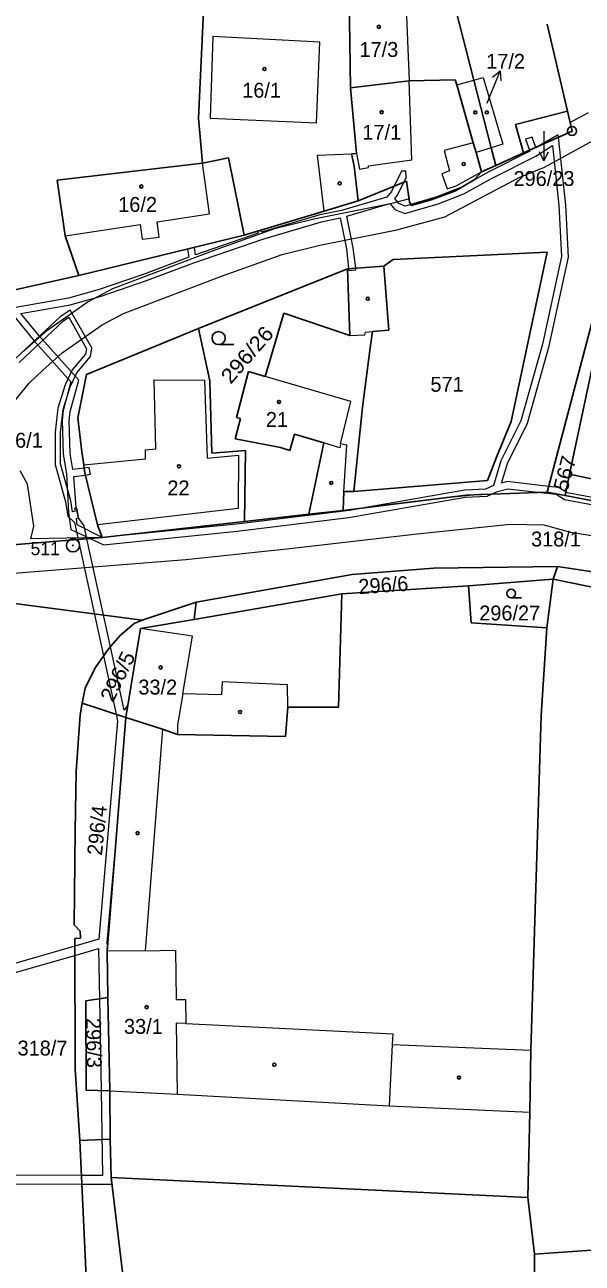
# Model space of a CAD drawing. Extents: x -769392 to -767038, y -1018329 to -1015269.
# Drawn here: x -768447.4 to -768383.8, y -1016351.8 to -1016210.5 of the extents above; entities that cross this region are included whole.
import ezdxf
from ezdxf.enums import TextEntityAlignment as Align

# ---------------------------------------------------------------- set-up
doc = ezdxf.new("R2010")
doc.units = 0
doc.header["$LTSCALE"] = 0.68
for name, color, linetype, lineweight in [('1', 7, 'Continuous', 25), ('13', 7, 'Continuous', 13), ('3', 7, 'Continuous', 25), ('4', 7, 'Continuous', 13), ('5', 7, 'Continuous', 25), ('7', 7, 'Continuous', 13), ('8', 7, 'Continuous', 25)]:
    doc.layers.add(name, color=color, linetype=linetype, lineweight=lineweight)
doc.layers.add('2', color=7, linetype='Continuous')

msp = doc.modelspace()

# ---------------------------------------------------------------- linework, layer by layer
at = {"layer": '1'}
for p, q in [((-768427.58, -1016221.15), (-768426.85, -1016205.24)), ((-768410.25, -1016217.66), (-768410.41, -1016207.35)), ((-768396.18, -1016216.78), (-768398.81, -1016206.49)), ((-768387.82, -1016210.42), (-768385.5, -1016220.32)), ((-768410.25, -1016217.66), (-768403.57, -1016216.87)), ((-768403.57, -1016216.87), (-768398.3, -1016216.77)), ((-768398.3, -1016216.77), (-768398.11, -1016217.33)), ((-768398.11, -1016217.33), (-768396.23, -1016223.95)), ((-768394.2, -1016224.52), (-768396.18, -1016216.78)), ((-768409.58, -1016225.18), (-768410.25, -1016217.66)), ((-768391.42, -1016221.87), (-768385.5, -1016220.32)), ((-768385.5, -1016220.32), (-768384.97, -1016222.6)), ((-768427.14, -1016226.27), (-768427.58, -1016221.15)), ((-768390.51, -1016225.1), (-768391.42, -1016221.87)), ((-768384.97, -1016222.6), (-768390.51, -1016225.1)), ((-768396.23, -1016223.95), (-768395.92, -1016225.04)), ((-768393.68, -1016226.53), (-768394.2, -1016224.52)), ((-768377.38, -1016224.21), (-768387.81, -1016263.79)), ((-768424.16, -1016225.64), (-768427.14, -1016226.27)), ((-768422.37, -1016234.48), (-768424.16, -1016225.64)), ((-768410.13, -1016225.19), (-768409.58, -1016225.18)), ((-768409.84, -1016226.61), (-768410.13, -1016225.19)), ((-768395.92, -1016225.04), (-768395.3, -1016227.26)), ((-768390.51, -1016225.1), (-768393.68, -1016226.53)), ((-768443.71, -1016228.21), (-768427.14, -1016226.27)), ((-768409.37, -1016230.58), (-768409.84, -1016226.61)), ((-768395.3, -1016227.26), (-768396.12, -1016228.18)), ((-768393.68, -1016226.53), (-768395.3, -1016227.26)), ((-768442.8, -1016234.55), (-768443.71, -1016228.21)), ((-768403.85, -1016228.31), (-768409.37, -1016230.58)), ((-768403.53, -1016230.66), (-768403.85, -1016228.31)), ((-768396.12, -1016228.18), (-768398.26, -1016229.41)), ((-768398.26, -1016229.41), (-768401.04, -1016230.45)), ((-768413.24, -1016231.74), (-768409.37, -1016230.58)), ((-768403.33, -1016231.11), (-768403.53, -1016230.66)), ((-768401.04, -1016230.45), (-768403.33, -1016231.11)), ((-768422.37, -1016234.48), (-768413.24, -1016231.74)), ((-768441.25, -1016239.08), (-768442.8, -1016234.55)), ((-768441.25, -1016239.08), (-768422.37, -1016234.48)), ((-768406.45, -1016238.03), (-768405.37, -1016237.26)), ((-768405.37, -1016237.26), (-768387.79, -1016236.4)), ((-768387.79, -1016236.4), (-768391.91, -1016255.72)), ((-768427.58, -1016245.12), (-768410.58, -1016238.33)), ((-768410.58, -1016238.33), (-768406.45, -1016238.03)), ((-768410.58, -1016238.33), (-768410.31, -1016245.94)), ((-768405.88, -1016245.31), (-768406.45, -1016238.03)), ((-768449.37, -1016240.92), (-768441.25, -1016239.08)), ((-768385.26, -1016261.73), (-768380.52, -1016239.41)), ((-768417.87, -1016243.39), (-768419.98, -1016250.59)), ((-768410.31, -1016245.94), (-768417.87, -1016243.39)), ((-768440.38, -1016250.37), (-768427.58, -1016245.12)), ((-768426.31, -1016251.11), (-768427.58, -1016245.12)), ((-768407.99, -1016247.34), (-768407.74, -1016245.47)), ((-768407.74, -1016245.47), (-768405.88, -1016245.31)), ((-768408.88, -1016254.11), (-768407.99, -1016247.34)), ((-768441.37, -1016255.32), (-768440.38, -1016250.37)), ((-768426.05, -1016259.35), (-768426.31, -1016251.11)), ((-768421.9, -1016250.03), (-768423.26, -1016255.27)), ((-768419.98, -1016250.59), (-768421.9, -1016250.03)), ((-768409.86, -1016263.72), (-768408.88, -1016254.11)), ((-768440.91, -1016259.2), (-768441.37, -1016255.32)), ((-768422.79, -1016255.4), (-768423.41, -1016257.71)), ((-768423.26, -1016255.27), (-768422.79, -1016255.4)), ((-768391.91, -1016255.72), (-768393.57, -1016259.81)), ((-768423.41, -1016257.71), (-768418.24, -1016258.71)), ((-768417.16, -1016259.03), (-768416.62, -1016257.2)), ((-768416.62, -1016257.2), (-768413.3, -1016258.18)), ((-768413.3, -1016258.18), (-768414.99, -1016266.32)), ((-768440.69, -1016260.68), (-768440.91, -1016259.2)), ((-768422.24, -1016259.04), (-768426.05, -1016259.35)), ((-768422.34, -1016267.16), (-768422.24, -1016259.04)), ((-768418.24, -1016258.71), (-768417.16, -1016259.03)), ((-768393.57, -1016259.81), (-768394.63, -1016262.48)), ((-768440.55, -1016261.58), (-768440.69, -1016260.68)), ((-768439.11, -1016267.52), (-768440.55, -1016261.58)), ((-768394.63, -1016262.48), (-768409.86, -1016263.72)), ((-768385.75, -1016264.19), (-768385.26, -1016261.73)), ((-768375.87, -1016263.76), (-768385.26, -1016261.73)), ((-768411.09, -1016265.88), (-768410.99, -1016263.74)), ((-768410.99, -1016263.74), (-768409.86, -1016263.72)), ((-768397.04, -1016264.15), (-768395.26, -1016264.06)), ((-768395.26, -1016264.06), (-768387.81, -1016263.79)), ((-768387.81, -1016263.79), (-768385.75, -1016264.19)), ((-768411.09, -1016265.88), (-768397.04, -1016264.15)), ((-768361, -1016268.94), (-768385.75, -1016264.19)), ((-768422.34, -1016267.16), (-768414.99, -1016266.32)), ((-768414.99, -1016266.32), (-768411.09, -1016265.88)), ((-768438.59, -1016268.98), (-768439.11, -1016267.52)), ((-768438.59, -1016268.98), (-768422.34, -1016267.16)), ((-768453.04, -1016270.15), (-768438.59, -1016268.98)), ((-768410.05, -1016273.2), (-768400.79, -1016272.48)), ((-768400.79, -1016272.48), (-768386.61, -1016272.27)), ((-768386.61, -1016272.27), (-768387.13, -1016273.73)), ((-768386.61, -1016272.27), (-768375.4, -1016273.98)), ((-768427.87, -1016276.35), (-768410.05, -1016273.2)), ((-768387.13, -1016273.73), (-768396.8, -1016274.47)), ((-768387.84, -1016279.26), (-768387.13, -1016273.73)), ((-768381.35, -1016274.89), (-768387.13, -1016273.73)), ((-768411.23, -1016275.39), (-768428.08, -1016278.34)), ((-768411.63, -1016288.32), (-768411.23, -1016275.39)), ((-768396.8, -1016274.47), (-768411.23, -1016275.39)), ((-768396.8, -1016274.47), (-768396.48, -1016278.7)), ((-768434, -1016278.4), (-768453.2, -1016275.91)), ((-768434, -1016278.4), (-768427.87, -1016276.35)), ((-768427.87, -1016276.35), (-768428.08, -1016278.34)), ((-768434.93, -1016278.8), (-768436.49, -1016280.13)), ((-768434.19, -1016279.35), (-768435.88, -1016289.49)), ((-768434.93, -1016278.8), (-768434, -1016278.4)), ((-768428.08, -1016278.34), (-768434.19, -1016279.35)), ((-768396.48, -1016278.7), (-768387.84, -1016279.26)), ((-768387.84, -1016279.26), (-768388.49, -1016289.29)), ((-768436.49, -1016280.13), (-768437.84, -1016281.64)), ((-768437.84, -1016281.64), (-768439.39, -1016283.83)), ((-768439.39, -1016283.83), (-768440.51, -1016286.17)), ((-768440.51, -1016286.17), (-768440.85, -1016287.88)), ((-768440.85, -1016287.88), (-768441.11, -1016289.2)), ((-768440.85, -1016287.88), (-768435.88, -1016289.49)), ((-768441.55, -1016295.66), (-768441.11, -1016289.2)), ((-768435.88, -1016289.49), (-768438.02, -1016316.15)), ((-768435.88, -1016289.49), (-768431.68, -1016290.85)), ((-768417.65, -1016291.66), (-768417.4, -1016288.34)), ((-768417.4, -1016288.34), (-768413.22, -1016288.31)), ((-768413.22, -1016288.31), (-768411.63, -1016288.32)), ((-768388.49, -1016289.29), (-768389.67, -1016327.44)), ((-768431.68, -1016290.85), (-768430, -1016291.45)), ((-768430, -1016291.45), (-768417.65, -1016291.66)), ((-768441.68, -1016302.44), (-768441.55, -1016295.66)), ((-768441.78, -1016313.16), (-768441.68, -1016302.44)), ((-768441.09, -1016313.88), (-768441.78, -1016313.16)), ((-768441.72, -1016314.73), (-768441.06, -1016314.69)), ((-768441.68, -1016329.61), (-768441.72, -1016314.73)), ((-768441.06, -1016314.69), (-768441.09, -1016313.88)), ((-768438.02, -1016316.15), (-768437.94, -1016321.46)), ((-768437.94, -1016321.46), (-768440.44, -1016321.83)), ((-768440.44, -1016321.83), (-768440.39, -1016332.01)), ((-768437.7, -1016332.1), (-768437.94, -1016321.46)), ((-768389.67, -1016327.44), (-768389.78, -1016334.51)), ((-768441.14, -1016337.77), (-768441.68, -1016329.61)), ((-768440.39, -1016332.01), (-768437.7, -1016332.1)), ((-768437.66, -1016337.59), (-768437.7, -1016332.1)), ((-768389.78, -1016334.51), (-768390.03, -1016344.27)), ((-768437.66, -1016337.59), (-768441.14, -1016337.77)), ((-768441.14, -1016337.77), (-768438.23, -1016399.9)), ((-768437.56, -1016341.98), (-768437.66, -1016337.59)), ((-768390.03, -1016344.27), (-768437.56, -1016341.98)), ((-768433.06, -1016378.94), (-768437.56, -1016341.98)), ((-768389.26, -1016350.71), (-768390.03, -1016344.27)), ((-768367.21, -1016349.21), (-768389.26, -1016350.71)), ((-768389.23, -1016362.23), (-768389.26, -1016350.71))]:
    msp.add_line(p, q, dxfattribs=at)
at = {"layer": '13'}
for points in [[(-768383.12, -1016220.51), (-768385.18, -1016221.63), (-768384.97, -1016222.6), (-768390.51, -1016225.1), (-768393.68, -1016226.53), (-768395.3, -1016227.26), (-768396.12, -1016228.18), (-768398.26, -1016229.41), (-768401.04, -1016230.45), (-768403.33, -1016231.11), (-768403.53, -1016230.66), (-768403.57, -1016230.35), (-768403.66, -1016230.38), (-768405.67, -1016230.9), (-768414.43, -1016232.64), (-768418.93, -1016233.75), (-768426.02, -1016236.29), (-768437.41, -1016240.62), (-768440.17, -1016242.07), (-768445.06, -1016245.52), (-768447.47, -1016247.67)], [(-768449.23, -1016254.2), (-768446.9, -1016251.36), (-768445.39, -1016249.93), (-768443.15, -1016247.92), (-768438.57, -1016244.69), (-768436.15, -1016243.42), (-768424.96, -1016239.17), (-768418.04, -1016236.69), (-768413.76, -1016235.63), (-768404.97, -1016233.88), (-768399.48, -1016232.38), (-768390.91, -1016227.86), (-768388.12, -1016226.71), (-768381.36, -1016223.05)], [(-768449.33, -1016242.84), (-768446.37, -1016246.5), (-768442.14, -1016251.21), (-768443.02, -1016254.47), (-768443.13, -1016255.62), (-768443.05, -1016259.47), (-768442.65, -1016261.7), (-768442.43, -1016266.13), (-768442.17, -1016268.06), (-768439.97, -1016269.09), (-768438.59, -1016268.98), (-768441.43, -1016267.52), (-768441.53, -1016266.82), (-768441.3, -1016266.77), (-768441.56, -1016265.54), (-768441.83, -1016262.03), (-768440.49, -1016261.84), (-768440.55, -1016261.58), (-768440.63, -1016261.05), (-768441.92, -1016261.23), (-768442.25, -1016259.39), (-768442.33, -1016255.65), (-768442.23, -1016254.61), (-768441.26, -1016251.02), (-768445.77, -1016245.98), (-768447.85, -1016243.43), (-768442.23, -1016242.44), (-768438.69, -1016241.43), (-768433.53, -1016239.66), (-768428.11, -1016237.62), (-768420.24, -1016234.93), (-768413.55, -1016232.94), (-768411.43, -1016232.52), (-768410.72, -1016236.04), (-768410.48, -1016238.23), (-768410.47, -1016238.32), (-768409.65, -1016238.26), (-768409.93, -1016235.91), (-768410.65, -1016232.32), (-768405.77, -1016230.88), (-768405.2, -1016231.56), (-768404.03, -1016232.01), (-768400.24, -1016230.92), (-768397.33, -1016229.77), (-768394.16, -1016228), (-768389.09, -1016225.45), (-768387.21, -1016224.24), (-768386.47, -1016231.1), (-768386.17, -1016236.91), (-768388.34, -1016246.91), (-768390.8, -1016255.65), (-768393.08, -1016260.23), (-768393.94, -1016263.05), (-768394.84, -1016263.44), (-768397.21, -1016263.56), (-768408.48, -1016265.56), (-768397.04, -1016264.15), (-768395.26, -1016264.06), (-768394.16, -1016264.02), (-768393.48, -1016263.72), (-768392.3, -1016263.4), (-768388.54, -1016263.82), (-768387.81, -1016263.79), (-768387.64, -1016263.14), (-768392.38, -1016262.59), (-768393.02, -1016262.76), (-768392.34, -1016260.53)], [(-768388.72, -1016224.29), (-768389.08, -1016224.5), (-768389.09, -1016224.46), (-768389.82, -1016224.79), (-768389.78, -1016224.91), (-768394.53, -1016227.29), (-768397.67, -1016229.04), (-768400.5, -1016230.16), (-768403.38, -1016230.99), (-768403.99, -1016231.16), (-768404.72, -1016230.88), (-768405.2, -1016230.31), (-768404.89, -1016229.92), (-768403.88, -1016227.91), (-768403.94, -1016227.19), (-768404.41, -1016227.19), (-768405.57, -1016229.48), (-768406.09, -1016230.14), (-768411.26, -1016231.66), (-768413.75, -1016232.17), (-768420.42, -1016234.15), (-768420.5, -1016233.91), (-768420.84, -1016234.02), (-768420.77, -1016234.26), (-768427.92, -1016236.71), (-768428.05, -1016235.88), (-768428.83, -1016236.07), (-768428.68, -1016236.99), (-768433.8, -1016238.91), (-768438.93, -1016240.67), (-768442.41, -1016241.66), (-768448.42, -1016242.72)], [(-768392.34, -1016260.53), (-768390.05, -1016255.94), (-768387.56, -1016247.1), (-768385.37, -1016236.98), (-768385.67, -1016231.04), (-768386.51, -1016223.3), (-768388.72, -1016224.29)], [(-768448.05, -1016249), (-768442.98, -1016244.25), (-768442.38, -1016243.84), (-768440.38, -1016247.43), (-768440.47, -1016248.06), (-768442, -1016249.85), (-768442.81, -1016251.57), (-768443.63, -1016254.23), (-768443.94, -1016256.96), (-768443.95, -1016260.66), (-768442.75, -1016264.89), (-768442.49, -1016266.53), (-768441.75, -1016267.25), (-768441.33, -1016269.2), (-768440.33, -1016269.12), (-768440.65, -1016267.64), (-768441.26, -1016266.82), (-768441.49, -1016265.63), (-768441.73, -1016265.68), (-768441.67, -1016265.97), (-768441.97, -1016266.03), (-768442.17, -1016264.77), (-768443.35, -1016260.58), (-768443.34, -1016256.99), (-768443.04, -1016254.35), (-768442.25, -1016251.78), (-768441.49, -1016250.18), (-768439.91, -1016248.32), (-768439.75, -1016247.32), (-768442.25, -1016243.02), (-768443.36, -1016243.78), (-768448.43, -1016248.53)], [(-768453.04, -1016270.15), (-768438.59, -1016268.98), (-768446.72, -1016269.13), (-768446.37, -1016267.68), (-768447.12, -1016262.9), (-768447.95, -1016261.35)], [(-768265.62, -1016295.35), (-768269.5, -1016291.1), (-768273.62, -1016286.59), (-768273.53, -1016285.32), (-768285.46, -1016283.1), (-768307.82, -1016279.73), (-768319.82, -1016277.09), (-768333.82, -1016274.33), (-768336.54, -1016273.63), (-768337.71, -1016273.41), (-768361, -1016268.94), (-768369.19, -1016267.37), (-768384.81, -1016264.37), (-768387.74, -1016263.85), (-768388.8, -1016263.83), (-768395.26, -1016264.06), (-768395.51, -1016264.07), (-768399.68, -1016264.48), (-768411.09, -1016265.88), (-768414.99, -1016266.32), (-768422.34, -1016267.16), (-768438.59, -1016268.98), (-768453.04, -1016270.15)], [(-768449.1, -1016273.07), (-768429.05, -1016271.47), (-768417.15, -1016270.23), (-768402.63, -1016268.55), (-768392.04, -1016267.45), (-768388.19, -1016267.54), (-768385.13, -1016268.37), (-768379.1, -1016269.33), (-768364.82, -1016271.66), (-768346.84, -1016274.82), (-768334.63, -1016277.94), (-768320.58, -1016280.72), (-768308.49, -1016283.37), (-768286.07, -1016286.75), (-768276.15, -1016288.44), (-768270.12, -1016294.69), (-768266.07, -1016295.75)]]:
    msp.add_lwpolyline(points, dxfattribs=at)
for points in [[(-768388.72, -1016224.29), (-768386.51, -1016223.3), (-768386.54, -1016223.03)], [(-768390.29, -1016223.54), (-768389.82, -1016224.79), (-768389.09, -1016224.46), (-768389.52, -1016223.31)], [(-768409.63, -1016238.45), (-768409.65, -1016238.26), (-768410.47, -1016238.32), (-768410.45, -1016238.51)], [(-768440.05, -1016260.97), (-768440.63, -1016261.05), (-768440.55, -1016261.58), (-768440.49, -1016261.84), (-768439.92, -1016261.76)], [(-768397.04, -1016264.15), (-768408.48, -1016265.56), (-768410.35, -1016265.89), (-768423.27, -1016267.44), (-768438.59, -1016268.98), (-768439.97, -1016269.09), (-768438.44, -1016269.81), (-768423.18, -1016268.24), (-768410.47, -1016266.7), (-768397.12, -1016264.36), (-768394.66, -1016264.24), (-768394.16, -1016264.02)], [(-768388.54, -1016263.82), (-768386.79, -1016264.01), (-768385.83, -1016264.62), (-768376.82, -1016266.29), (-768374.34, -1016266.62), (-768375.51, -1016273.96), (-768375.4, -1016273.98), (-768374.73, -1016274.11), (-768373.54, -1016266.73), (-768369.19, -1016267.37), (-768385.75, -1016264.19), (-768387.81, -1016263.79)], [(-768386.47, -1016263.27), (-768387.64, -1016263.14), (-768387.81, -1016263.79), (-768385.75, -1016264.19), (-768369.19, -1016267.37), (-768361.27, -1016268.53), (-768360.93, -1016268.59), (-768360.79, -1016267.78), (-768360.84, -1016267.77), (-768373.79, -1016265.88), (-768376.3, -1016265.55), (-768375.77, -1016263.43), (-768376.53, -1016263.24), (-768377.1, -1016265.43), (-768385.53, -1016263.86)], [(-768438.44, -1016282.48), (-768437.84, -1016281.64), (-768437.65, -1016281.43), (-768440.33, -1016269.12), (-768441.33, -1016269.2)], [(-768436.99, -1016289.13), (-768435.88, -1016289.49), (-768435.64, -1016288.06), (-768436.07, -1016288.67), (-768437.65, -1016281.43), (-768437.84, -1016281.64), (-768438.44, -1016282.48)], [(-768439, -1016315.85), (-768438.9, -1016321.6), (-768437.94, -1016321.46), (-768438.02, -1016316.15), (-768437.97, -1016315.57), (-768438.01, -1016315.19), (-768437.07, -1016304.33), (-768435.88, -1016289.49), (-768436.99, -1016289.13), (-768436.82, -1016289.92), (-768438.98, -1016314.8), (-768441.72, -1016315.59), (-768441.71, -1016316.64)], [(-768441.71, -1016316.64), (-768441.72, -1016315.59), (-768450.13, -1016318.03), (-768450.12, -1016319.07)], [(-768438.9, -1016321.6), (-768438.71, -1016332.07), (-768437.7, -1016332.1), (-768437.94, -1016321.46)], [(-768438.53, -1016341.74), (-768440.95, -1016341.74), (-768440.91, -1016342.74), (-768437.47, -1016342.74), (-768437.56, -1016341.98), (-768437.66, -1016337.59), (-768437.7, -1016332.1), (-768438.71, -1016332.07)], [(-768440.91, -1016342.74), (-768440.95, -1016341.74), (-768449.38, -1016341.72), (-768449.35, -1016342.72)]]:
    msp.add_lwpolyline(points, close=True, dxfattribs=at)
at = {"layer": '3'}
for p, q in [((-768425.293, -1016246.97), (-768423.543, -1016246.97)), ((-768391.915, -1016275.86), (-768390.743, -1016275.86))]:
    msp.add_line(p, q, dxfattribs=at)
for centre, radius in [((-768425.2929, -1016246.2198), 0.75), ((-768391.9152, -1016275.3574), 0.5025)]:
    msp.add_circle(centre, radius, dxfattribs=at)
at = {"layer": '4'}
for p, q in [((-768403.95, -1016207.64), (-768403.57, -1016216.87)), ((-768425.96, -1016211.8), (-768426.27, -1016221.13)), ((-768413.74, -1016212.46), (-768425.96, -1016211.8)), ((-768414.14, -1016221.65), (-768413.74, -1016212.46)), ((-768403.23, -1016225.89), (-768403.57, -1016216.87)), ((-768398.11, -1016217.33), (-768396.18, -1016216.78)), ((-768396.18, -1016216.78), (-768395.11, -1016216.48)), ((-768395.11, -1016216.48), (-768392.86, -1016224.11)), ((-768426.27, -1016221.13), (-768414.14, -1016221.65)), ((-768396.23, -1016223.95), (-768399.57, -1016224.83)), ((-768394.2, -1016224.52), (-768395.92, -1016225.04)), ((-768392.86, -1016224.11), (-768394.2, -1016224.52)), ((-768414.02, -1016225.37), (-768410.13, -1016225.19)), ((-768413.24, -1016231.74), (-768414.02, -1016225.37)), ((-768409.58, -1016225.18), (-768409.21, -1016226.96)), ((-768408.21, -1016226.58), (-768403.23, -1016225.89)), ((-768399.57, -1016224.83), (-768398.95, -1016227.13)), ((-768426.35, -1016232.03), (-768427.14, -1016226.27)), ((-768409.21, -1016226.96), (-768408.2, -1016226.77)), ((-768408.2, -1016226.77), (-768408.21, -1016226.58)), ((-768398.95, -1016227.13), (-768399.83, -1016227.5)), ((-768398.2, -1016228.84), (-768395.3, -1016227.26)), ((-768399.83, -1016227.5), (-768399.21, -1016229.19)), ((-768399.21, -1016229.19), (-768398.2, -1016228.84)), ((-768432.29, -1016232.97), (-768426.35, -1016232.03)), ((-768432.07, -1016234.69), (-768432.29, -1016232.97)), ((-768442.8, -1016234.55), (-768434.26, -1016233.26)), ((-768434.26, -1016233.26), (-768434.02, -1016234.93)), ((-768434.02, -1016234.93), (-768432.07, -1016234.69)), ((-768408.62, -1016245.84), (-768408.55, -1016245.54)), ((-768408.55, -1016245.54), (-768407.74, -1016245.47)), ((-768410.31, -1016245.94), (-768408.62, -1016245.84)), ((-768432.64, -1016250.97), (-768426.89, -1016251.01)), ((-768432.45, -1016258.87), (-768432.64, -1016250.97)), ((-768426.89, -1016251.01), (-768426.6, -1016259.91)), ((-768410.19, -1016253.46), (-768419.98, -1016250.59)), ((-768411.38, -1016258.3), (-768410.19, -1016253.46)), ((-768411.46, -1016258.73), (-768413.3, -1016258.18)), ((-768411.38, -1016258.3), (-768411.46, -1016258.73)), ((-768410.67, -1016258.44), (-768411.38, -1016258.3)), ((-768410.99, -1016263.74), (-768410.67, -1016258.44)), ((-768433.65, -1016258.98), (-768432.45, -1016258.87)), ((-768433.62, -1016260), (-768433.65, -1016258.98)), ((-768426.6, -1016259.91), (-768423.03, -1016259.59)), ((-768423.03, -1016259.59), (-768423.05, -1016265.66)), ((-768440.69, -1016260.68), (-768433.62, -1016260)), ((-768423.05, -1016265.66), (-768439.11, -1016267.52)), ((-768428.28, -1016280.23), (-768434.19, -1016279.35)), ((-768429.37, -1016286.8), (-768428.28, -1016280.23)), ((-768424.9, -1016285.44), (-768424.96, -1016286.9)), ((-768417.44, -1016285.77), (-768424.9, -1016285.44)), ((-768417.4, -1016288.34), (-768417.44, -1016285.77)), ((-768429.37, -1016286.8), (-768429.98, -1016290.35)), ((-768424.96, -1016286.9), (-768429.37, -1016286.8)), ((-768431.68, -1016290.85), (-768433.67, -1016316.14)), ((-768429.98, -1016290.35), (-768430, -1016291.45)), ((-768433.67, -1016316.14), (-768438.02, -1016316.15)), ((-768433.67, -1016316.14), (-768430.23, -1016316.06)), ((-768430.23, -1016316.06), (-768430.15, -1016321.69)), ((-768430.15, -1016321.69), (-768429.06, -1016321.69)), ((-768429.06, -1016321.69), (-768429.05, -1016324.42)), ((-768430.12, -1016324.37), (-768430.03, -1016332.49)), ((-768429.05, -1016324.42), (-768430.12, -1016324.37)), ((-768429.05, -1016324.42), (-768405.42, -1016325.61)), ((-768405.42, -1016325.61), (-768405.48, -1016326.8)), ((-768405.48, -1016326.8), (-768405.83, -1016333.82)), ((-768405.48, -1016326.8), (-768389.67, -1016327.44)), ((-768437.7, -1016332.1), (-768430.03, -1016332.49)), ((-768430.03, -1016332.49), (-768405.83, -1016333.82)), ((-768405.83, -1016333.82), (-768389.78, -1016334.51))]:
    msp.add_line(p, q, dxfattribs=at)
at = {"layer": '5'}
for centre in [(-768407.0168, -1016210.7092), (-768420.0768, -1016215.5292), (-768406.6868, -1016220.4492), (-768396.0068, -1016220.4792), (-768394.6868, -1016220.4792), (-768397.3268, -1016226.3692), (-768434.1068, -1016228.9292), (-768411.4768, -1016228.5692), (-768408.2768, -1016241.7292), (-768418.3968, -1016253.4992), (-768429.8168, -1016260.8492), (-768412.4468, -1016262.7392), (-768431.9068, -1016283.7992), (-768422.8468, -1016288.8692), (-768434.5468, -1016302.6992), (-768433.4968, -1016322.5492), (-768418.9468, -1016329.1192), (-768397.8568, -1016330.5792)]:
    msp.add_circle(centre, 0.175, dxfattribs=at)
at = {"layer": '7'}
for p, q in [((-768393.186, -1016215.758), (-768394.025, -1016216.498)), ((-768388.17, -1016225.991), (-768387.669, -1016224.99))]:
    msp.add_line(p, q, dxfattribs=at)
for points in [[(-768394.67, -1016219.43), (-768394.31, -1016218.54), (-768393.186, -1016215.758), (-768393.097, -1016216.874)], [(-768388.17, -1016222.6), (-768388.17, -1016222.99), (-768388.17, -1016225.991), (-768388.671, -1016224.99)]]:
    msp.add_lwpolyline(points, dxfattribs=at)
at = {"layer": '8'}
for centre, radius in [((-768384.97, -1016222.5999), 0.5), ((-768384.97, -1016222.5999), 0.0303), ((-768441.91, -1016269.8698), 0.75), ((-768441.91, -1016269.8698), 0.03)]:
    msp.add_circle(centre, radius, dxfattribs=at)

# ---------------------------------------------------------------- texts
at = {"layer": '2'}
for s, p in [('17/3', (-768407.009, -1016214.145)), ('17/2', (-768392.549, -1016215.495)), ('16/1', (-768420.389, -1016218.795)), ('17/1', (-768406.679, -1016223.595)), ('296/23', (-768388.17, -1016228.865)), ('16/2', (-768434.539, -1016231.825)), ('571', (-768399.229, -1016252.345)), ('21', (-768418.639, -1016256.355)), ('296/1', (-768448.2, -1016258.725)), ('22', (-768429.879, -1016264.165)), ('318/1', (-768386.8, -1016269.995)), ('296/27', (-768392.08, -1016278.435)), ('33/2', (-768432.239, -1016286.885)), ('33/1', (-768433.879, -1016325.595)), ('318/7', (-768445.39, -1016328.065))]:
    msp.add_text(s, height=1.7, dxfattribs=at).set_placement(p, align=Align.CENTER)
for s, rotation, width, p in [('296/26', 49, 1.1, (-768421.4022, -1016248.6741)), ('567', 75, 1.05, (-768384.9787, -1016261.868)), ('296/5', 64, 1.05, (-768436.0454, -1016285.1966))]:
    msp.add_text(s, height=1.7, rotation=rotation, dxfattribs=dict(at, width=width)).set_placement(p, align=Align.CENTER)
for s, rotation, p in [('296/6', 4, (-768406.4393, -1016275.241)), ('296/4', 84, (-768438.3218, -1016302.4683)), ('296/3', 271, (-768440.3744, -1016326.6442))]:
    msp.add_text(s, height=1.7, rotation=rotation, dxfattribs=at).set_placement(p, align=Align.CENTER)
at = {"layer": '8'}
msp.add_text('511', height=1.5, dxfattribs=at).set_placement((-768443.409, -1016270.987), align=Align.RIGHT)

doc.saveas('drawing.dxf')
